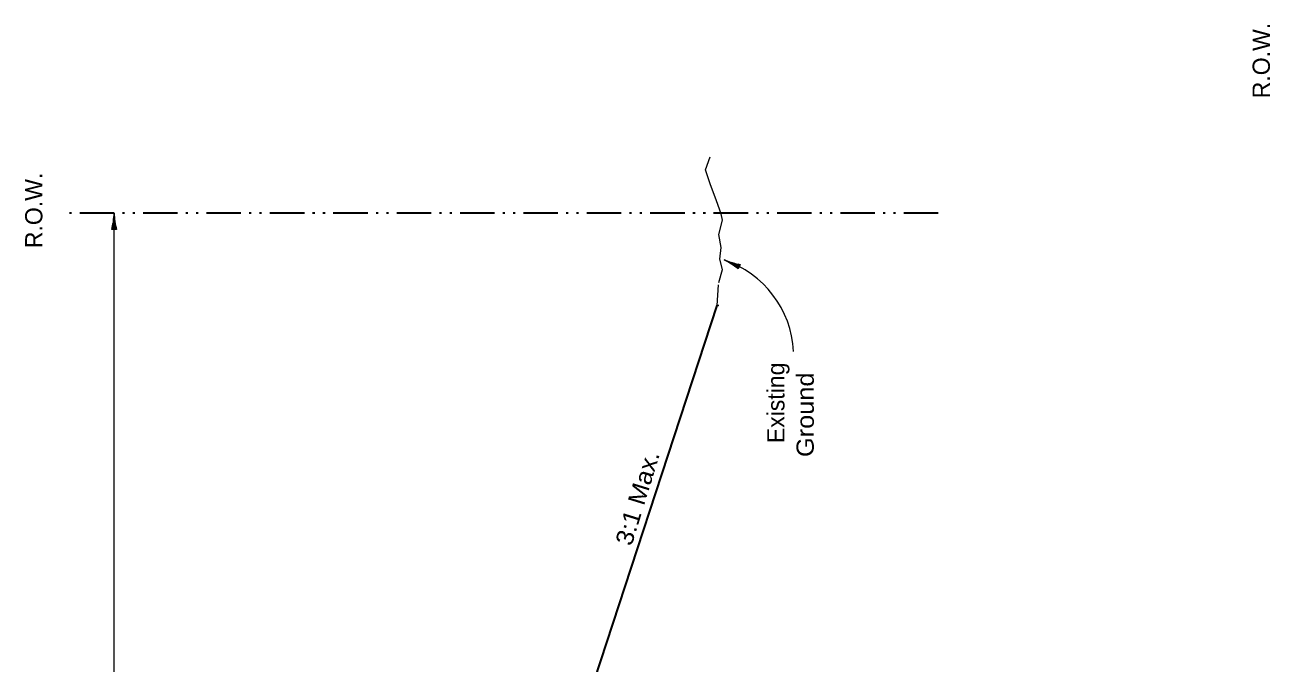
# Model space of a CAD drawing. Extents: x 2363427 to 2368559, y 6957299 to 6980140.
# Drawn here: x 2363619 to 2364631, y 6959583 to 6960102 of the extents above; entities that cross this region are included whole.
import ezdxf
from ezdxf.enums import TextEntityAlignment as Align

# ---------------------------------------------------------------- set-up
doc = ezdxf.new("R2010")
doc.units = 0
doc.header["$LTSCALE"] = 5.6
doc.linetypes.add('DASH_DOUBLE_DOT', pattern=[9.2, 5, -1.2, 0.3, -1.2, 0.3, -1.2])
doc.linetypes.add('MEDIUM_DASHED', pattern=[4.5, 3, -1.5])
for name, color, linetype, lineweight in [('2', 7, 'Continuous', 13), ('3', 7, 'Continuous', 35), ('4', 7, 'Continuous', 13), ('6', 7, 'Continuous', 13)]:
    doc.layers.add(name, color=color, linetype=linetype, lineweight=lineweight)

msp = doc.modelspace()

# ---------------------------------------------------------------- linework, layer by layer
at = {"layer": '2'}
for p, q in [((2364199.393, 6959905.309), (2364187.945, 6959910.487)), ((2364199.187, 6959904.853), (2364191.342, 6959908.401)), ((2364199.599, 6959905.765), (2364192.902, 6959908.793)), ((2364198.981, 6959904.399), (2364194.551, 6959906.401)), ((2364199.805, 6959906.221), (2364195.909, 6959907.983)), ((2364198.775, 6959903.943), (2364196.605, 6959904.925)), ((2364200.011, 6959906.677), (2364198.567, 6959907.329)), ((2364200.155, 6959906.995), (2364198.576, 6959903.505))]:
    msp.add_line(p, q, dxfattribs=at)
at = {"layer": '2', "linetype": 'MEDIUM_DASHED'}
msp.add_lwpolyline([(2364182.728, 6959873.609), (2364181.535, 6959873.773), (2364182.728, 6959892.551), (2364185.682, 6959903.075), (2364183.713, 6959911.493), (2364184.697, 6959920.963), (2364182.728, 6959931.487), (2364185.682, 6959943.063), (2364184.697, 6959948.323), (2364180.759, 6959958.847), (2364175.835, 6959972.527), (2364171.897, 6959984.103), (2364175.835, 6959994.625)], dxfattribs=at)
at = {"layer": '2'}
for centre, radius, start, end in [((2364160.609, 6959832.17), 82.963, 2.98496, 71.30193), ((2364154.252, 6959846.497), 72.212, 52.1346, 62.82065), ((2364213.694, 6959977.927), 72.212, 248.50777, 259.19382)]:
    msp.add_arc(centre, radius, start, end, dxfattribs=at)
at = {"layer": '3', "linetype": 'DASH_DOUBLE_DOT'}
msp.add_line((2364361.12, 6959948.819), (2363648.501, 6959948.819), dxfattribs=at)
at = {"layer": '3', "linetype": 'MEDIUM_DASHED', "lineweight": 13}
msp.add_line((2364181.535, 6959873.773), (2364182.413, 6959873.773), dxfattribs=at)
at = {"layer": '3'}
msp.add_lwpolyline([(2364050.199, 6959423.789), (2364066.723, 6959523.669), (2364181.535, 6959873.773)], dxfattribs=at)
at = {"layer": '6'}
for p, q in [((2363690.895, 6959935.507), (2363690.895, 6959944.117)), ((2363691.329, 6959073.103), (2363691.329, 6959948.819)), ((2363691.395, 6959935.507), (2363691.395, 6959948.071)), ((2363693.245, 6959935.507), (2363689.415, 6959935.507)), ((2363689.895, 6959935.507), (2363689.895, 6959937.889)), ((2363690.395, 6959935.507), (2363690.395, 6959940.369)), ((2363691.895, 6959935.507), (2363691.895, 6959942.857)), ((2363692.395, 6959935.507), (2363692.395, 6959939.783)), ((2363692.895, 6959935.507), (2363692.895, 6959937.093))]:
    msp.add_line(p, q, dxfattribs=at)
for centre, start, end in [((2363619.206, 6959952.401), 346.47039, 357.15644), ((2363763.453, 6959952.401), 182.84356, 193.52961)]:
    msp.add_arc(centre, 72.212, start, end, dxfattribs=at)

# ---------------------------------------------------------------- texts
at = {"layer": '4'}
for s, p in [('R.O.W.', (2364630.584, 6960072.821)), ('R.O.W.', (2363633.023, 6959951.005)), ('Existing ', (2364236.079, 6959797.213))]:
    msp.add_text(s, height=14, rotation=90, dxfattribs=at).set_placement(p, align=Align.CENTER)
at = {"layer": '4', "width": 1.1}
for s, rotation, p in [('Ground', 90, (2364259.949, 6959784.946)), ('3:1 Max.', 72.909, (2364123.362, 6959715.34))]:
    msp.add_text(s, height=14, rotation=rotation, dxfattribs=at).set_placement(p, align=Align.CENTER)

doc.saveas('drawing.dxf')
